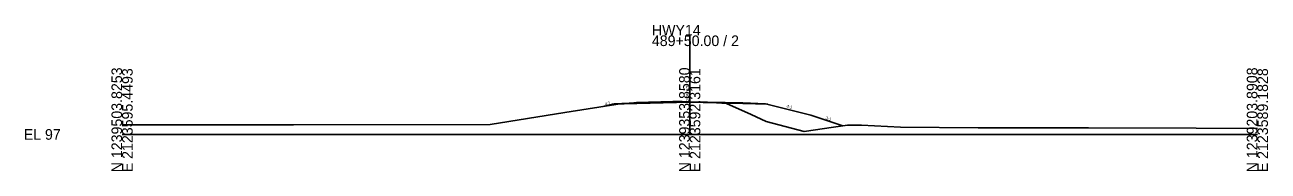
# Model space of a CAD drawing. Extents: x -26 to 303, y -10 to 11521.
# Drawn here: x -25.7 to 302.8, y 990.3 to 1028.9 of the extents above; entities that cross this region are included whole.
import ezdxf

# ---------------------------------------------------------------- set-up
doc = ezdxf.new("R2010")
doc.units = 0
for name, color, linetype in [('XS_CELL', 7, 'Continuous'), ('XS_P_FINISHED_GRADE', 7, 'Continuous'), ('XS_P_SUBGRADE_GRANULAR', 7, 'Continuous'), ('XS_P_SUBGRADE_LEVELING', 7, 'Continuous'), ('XS_P_TX_FS_BS', 7, 'Continuous'), ('XS_X_GROUND', 7, 'Continuous'), ('XS_X_GROUND_TX', 7, 'Continuous')]:
    doc.layers.add(name, color=color, linetype=linetype)

msp = doc.modelspace()

# ---------------------------------------------------------------- linework, layer by layer
at = {"layer": 'XS_CELL'}
for p, q in [((150, 1000), (150, 1026.14)), ((0, 1000), (150, 1000)), ((150, 1000), (300, 1000))]:
    msp.add_line(p, q, dxfattribs=at)
at = {"layer": 'XS_P_FINISHED_GRADE'}
for p, q in [((150, 1008.62), (136, 1008.34)), ((150, 1008.62), (164, 1008.34)), ((130, 1008.1), (127, 1007.35)), ((136, 1008.34), (130, 1008.1)), ((164, 1008.34), (170, 1008.1)), ((170, 1008.1), (182, 1005.1)), ((182, 1005.1), (190.48, 1002.27))]:
    msp.add_line(p, q, dxfattribs=at)
at = {"layer": 'XS_P_SUBGRADE_GRANULAR'}
for p, q in [((136, 1008.21), (129.4, 1007.95)), ((164, 1008.21), (170.6, 1007.95))]:
    msp.add_line(p, q, dxfattribs=at)
at = {"layer": 'XS_P_SUBGRADE_LEVELING'}
for p, q in [((150, 1008.49), (136, 1008.21)), ((136, 1008.21), (136, 1008.34)), ((150, 1008.49), (164, 1008.21)), ((164, 1008.21), (164, 1008.34))]:
    msp.add_line(p, q, dxfattribs=at)
at = {"layer": 'XS_X_GROUND'}
for p, q in [((135.95, 1008.43), (145.57, 1008.68)), ((145.57, 1008.68), (146.78, 1008.71)), ((146.78, 1008.71), (148.01, 1008.68)), ((148.01, 1008.68), (150, 1008.62)), ((150, 1008.62), (157.56, 1008.39)), ((97.26, 1002.63), (116.98, 1005.75)), ((116.98, 1005.75), (132.11, 1008.16)), ((132.11, 1008.16), (134.47, 1008.3)), ((134.47, 1008.3), (135.95, 1008.43)), ((157.56, 1008.39), (158.44, 1008.3)), ((158.44, 1008.3), (159.74, 1008.15)), ((159.74, 1008.15), (166.19, 1005.23)), ((0, 1002.49), (14.23, 1002.51)), ((14.23, 1002.51), (45.26, 1002.51)), ((45.26, 1002.51), (97.26, 1002.63)), ((166.19, 1005.23), (170.2, 1003.45)), ((170.2, 1003.45), (173.5, 1002.5)), ((173.5, 1002.5), (180.27, 1000.73)), ((188.03, 1001.89), (191.72, 1002.46)), ((191.72, 1002.46), (195.37, 1002.46)), ((195.37, 1002.46), (205.67, 1001.92)), ((180.27, 1000.73), (188.03, 1001.89)), ((205.67, 1001.92), (226.23, 1001.72)), ((226.23, 1001.72), (255.4, 1001.74)), ((255.4, 1001.74), (283.81, 1001.66)), ((283.81, 1001.66), (300, 1001.59))]:
    msp.add_line(p, q, dxfattribs=at)

# ---------------------------------------------------------------- texts
at = {"layer": 'XS_CELL'}
for s, p in [('HWY14', (140, 1026.14)), ('489+50.00 / 2', (140, 1023.34)), ('EL 97', (-26, 998.6))]:
    msp.add_text(s, height=2.8, dxfattribs=at).set_placement(p)
for s, p in [('N 1239503.8253', (0, 990)), ('E 2123595.4493', (2.8, 990)), ('N 1239353.8580', (150, 990)), ('E 2123592.3161', (152.8, 990)), ('N 1239203.8908', (300, 990)), ('E 2123589.1828', (302.8, 990))]:
    msp.add_text(s, height=2.8, rotation=90, dxfattribs=at).set_placement(p)
at = {"layer": 'XS_P_TX_FS_BS'}
for s, rotation, p in [('4:1', 14.0362, (127.63, 1007.63)), ('4:1', 345.9638, (175.5, 1007.1)), ('3:1', 341.5651, (185.82, 1004.04))]:
    msp.add_text(s, height=0.8, rotation=rotation, dxfattribs=at).set_placement(p)
at = {"layer": 'XS_X_GROUND_TX'}
msp.add_text('105.62', height=1, rotation=90, dxfattribs=at).set_placement((150, 1008.72))

doc.saveas('drawing.dxf')
